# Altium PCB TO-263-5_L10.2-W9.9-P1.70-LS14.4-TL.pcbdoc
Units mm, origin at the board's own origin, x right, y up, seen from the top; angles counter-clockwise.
Board outline 29.81 x 23.36 mm, 2 copper layers (Top Layer, Bottom Layer), stack 0 mm thick; 1 components, 0 nets, 6 pads, 0 vias.
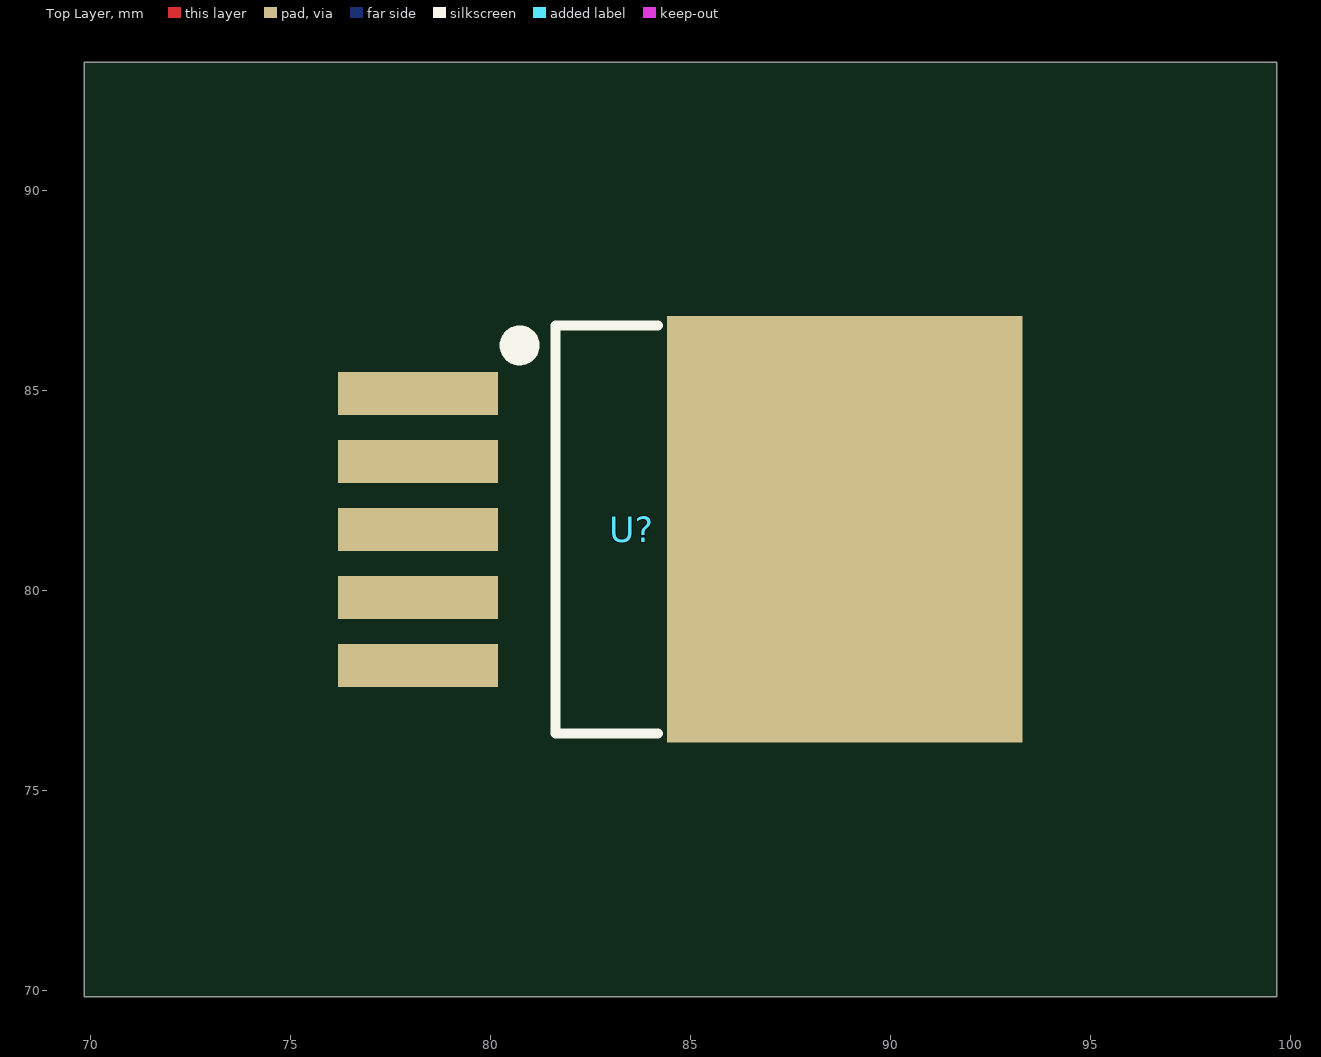
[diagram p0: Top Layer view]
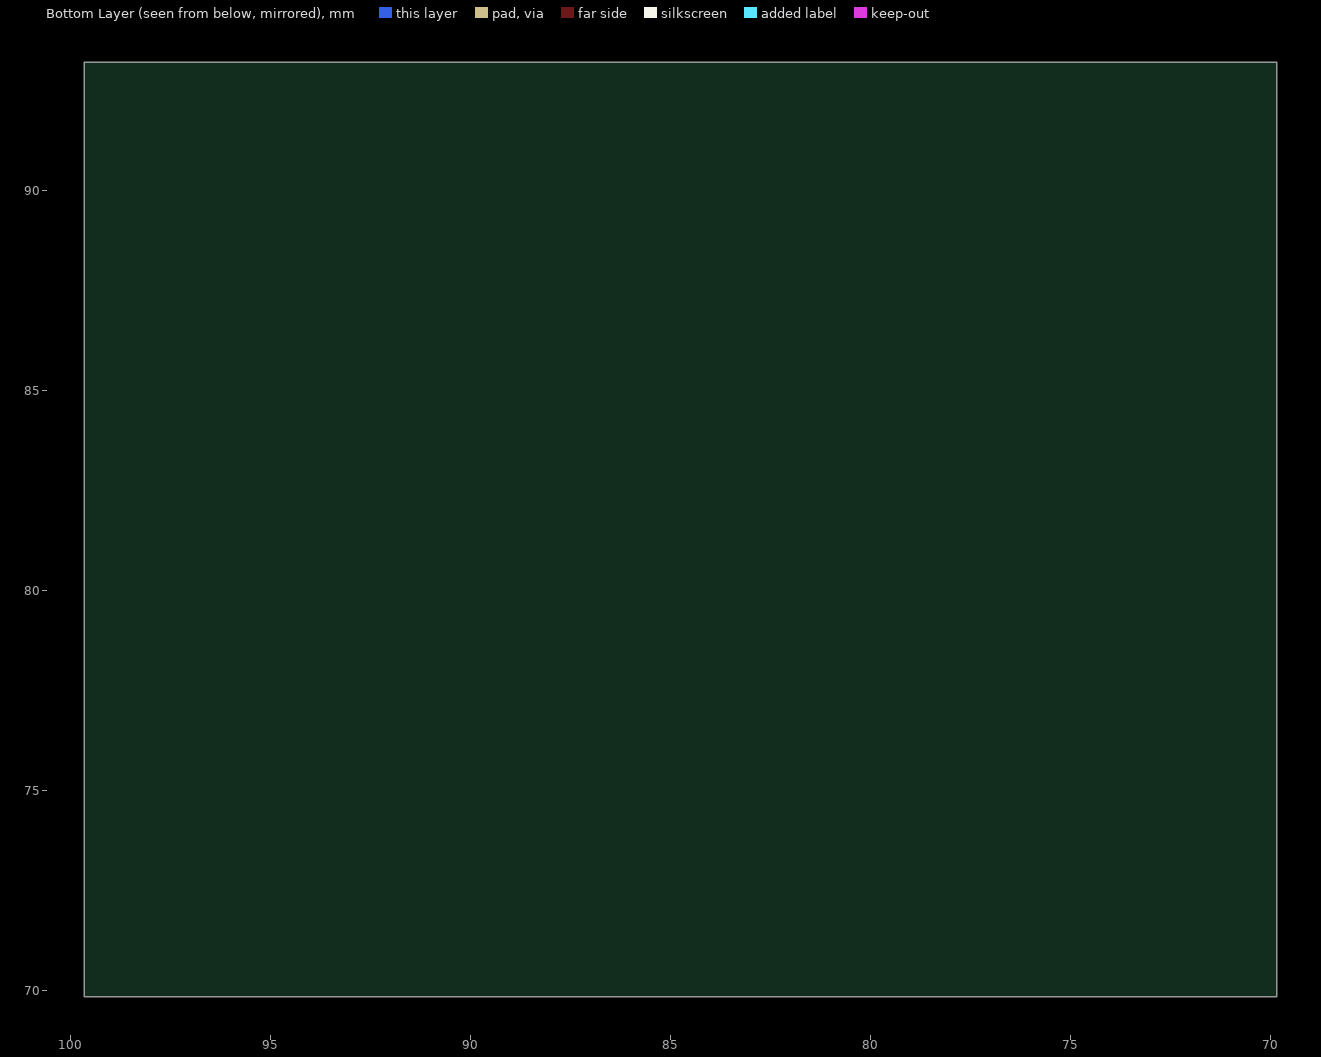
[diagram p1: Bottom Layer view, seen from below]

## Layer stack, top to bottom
Top Layer: signal copper (thickness not stored)
Bottom Layer: signal copper (thickness not stored)

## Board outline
99.663,69.85 69.85,69.85 69.85,93.21 99.663,93.21

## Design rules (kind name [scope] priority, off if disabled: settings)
PasteMaskExpansion "Paste Mask Expansion" [All] p1: expansion=0
SolderMaskExpansion "Solder Mask Expansion" [IsVia] p1: expansion=-25.4 istentingtop=TRUE
SolderMaskExpansion "Solder Mask Expansion" [All] p2: expansion=0.051 istentingtop=FALSE

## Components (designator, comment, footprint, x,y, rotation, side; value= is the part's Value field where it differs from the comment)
U? "" TO-263-5_L10.2-W9.9-P1.70-LS14.4-TL 83.534,81.53 r0 top

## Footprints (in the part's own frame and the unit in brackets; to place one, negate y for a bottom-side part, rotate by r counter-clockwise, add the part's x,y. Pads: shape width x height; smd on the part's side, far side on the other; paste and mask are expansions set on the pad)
TO-263-5_L10.2-W9.9-P1.70-LS14.4-TL [mil]
  rect 157.48x42.1 smd: 1(-210,133.84) 2(-210,66.92) 3(-210,0) 4(-210,-66.92) 5(-210,-133.84)
  rect 350x419.68 smd: 6(210,0)
  silkscreen extent -120,-201 26,201

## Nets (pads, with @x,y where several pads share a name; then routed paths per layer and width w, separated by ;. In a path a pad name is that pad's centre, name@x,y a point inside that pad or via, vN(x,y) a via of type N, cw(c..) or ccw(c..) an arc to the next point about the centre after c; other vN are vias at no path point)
pads on no net: U?.1 U?.2 U?.3 U?.4 U?.5 U?.6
